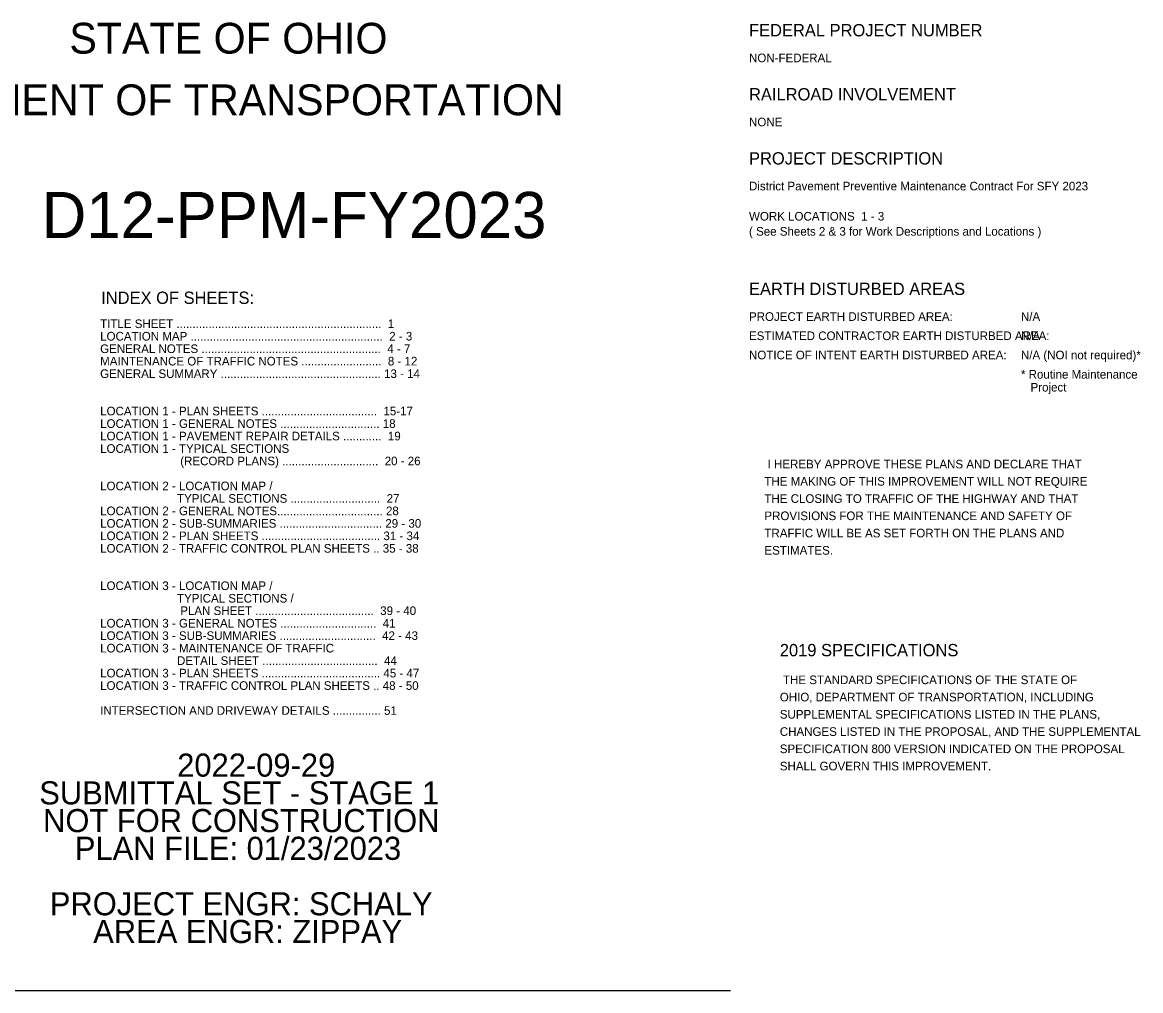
# Model space of a CAD drawing. Extents: x -59 to 82, y -3 to 49.
# Drawn here: x -47.61 to -29.45, y 3.5 to 19.22 of the extents above; entities that cross this region are included whole.
import ezdxf

# ---------------------------------------------------------------- set-up
doc = ezdxf.new("R2010")
doc.units = 0
for name, color, linetype in [('Default', 7, 'Continuous'), ('SH_Data', 7, 'Continuous'), ('SH_Text', 7, 'Continuous')]:
    doc.layers.add(name, color=color, linetype=linetype)

msp = doc.modelspace()

# ---------------------------------------------------------------- linework, layer by layer
at = {"layer": 'SH_Data'}
for p, q in [((-35.312, 7.218), (-35.312, 7.218)), ((-49.562, 3.503), (-36.112, 3.503))]:
    msp.add_line(p, q, dxfattribs=at)

# ---------------------------------------------------------------- texts
at = {"layer": 'Default'}
msp.add_text('D12-PPM-FY2023', height=0.75, dxfattribs=at).set_placement((-47.294, 15.717))
at = {"layer": 'SH_Data'}
for s, height, p in [('District Pavement Preventive Maintenance Contract For SFY 2023', 0.14, (-35.812, 16.492)), ('WORK LOCATIONS  1 - 3', 0.14, (-35.812, 16.002)), ('( See Sheets 2 & 3 for Work Descriptions and Locations )', 0.14, (-35.812, 15.757)), ('INDEX OF SHEETS:', 0.2, (-46.328, 14.649)), ('TITLE SHEET ................................................................  1', 0.14, (-46.345, 14.257)), ('LOCATION MAP ............................................................  2 - 3', 0.14, (-46.345, 14.055)), ('GENERAL NOTES ........................................................  4 - 7', 0.14, (-46.345, 13.852)), ('MAINTENANCE OF TRAFFIC NOTES .........................  8 - 12', 0.14, (-46.345, 13.65)), ('GENERAL SUMMARY .................................................. 13 - 14', 0.14, (-46.345, 13.447)), ('LOCATION 1 - PLAN SHEETS ....................................  15-17', 0.14, (-46.345, 12.84)), ('LOCATION 1 - GENERAL NOTES ............................... 18', 0.14, (-46.345, 12.637)), ('LOCATION 1 - PAVEMENT REPAIR DETAILS ............  19', 0.14, (-46.345, 12.435)), ('LOCATION 1 - TYPICAL SECTIONS', 0.14, (-46.345, 12.232)), ('                         (RECORD PLANS) ..............................  20 - 26', 0.14, (-46.345, 12.03)), (' I HEREBY APPROVE THESE PLANS AND DECLARE THAT', 0.14, (-35.562, 11.98)), ('THE MAKING OF THIS IMPROVEMENT WILL NOT REQUIRE', 0.14, (-35.562, 11.7)), ('LOCATION 2 - LOCATION MAP / ', 0.14, (-46.345, 11.625)), ('                        TYPICAL SECTIONS ............................  27', 0.14, (-46.345, 11.422)), ('THE CLOSING TO TRAFFIC OF THE HIGHWAY AND THAT', 0.14, (-35.562, 11.42)), ('LOCATION 2 - GENERAL NOTES................................. 28', 0.14, (-46.345, 11.22)), ('PROVISIONS FOR THE MAINTENANCE AND SAFETY OF', 0.14, (-35.562, 11.14)), ('LOCATION 2 - SUB-SUMMARIES ................................ 29 - 30', 0.14, (-46.345, 11.017)), ('LOCATION 2 - PLAN SHEETS ..................................... 31 - 34', 0.14, (-46.345, 10.815)), ('TRAFFIC WILL BE AS SET FORTH ON THE PLANS AND', 0.14, (-35.562, 10.86)), ('LOCATION 2 - TRAFFIC CONTROL PLAN SHEETS .. 35 - 38', 0.14, (-46.345, 10.612)), ('ESTIMATES.', 0.14, (-35.562, 10.58)), ('LOCATION 3 - LOCATION MAP /', 0.14, (-46.345, 10.005)), ('                        TYPICAL SECTIONS /', 0.14, (-46.345, 9.802)), ('                         PLAN SHEET .....................................  39 - 40', 0.14, (-46.345, 9.6)), ('LOCATION 3 - GENERAL NOTES ..............................  41', 0.14, (-46.345, 9.397)), ('LOCATION 3 - SUB-SUMMARIES ..............................  42 - 43', 0.14, (-46.345, 9.195)), ('LOCATION 3 - MAINTENANCE OF TRAFFIC', 0.14, (-46.345, 8.992)), ('                        DETAIL SHEET ....................................  44', 0.14, (-46.345, 8.79)), ('LOCATION 3 - PLAN SHEETS ..................................... 45 - 47', 0.14, (-46.345, 8.587)), ('LOCATION 3 - TRAFFIC CONTROL PLAN SHEETS .. 48 - 50', 0.14, (-46.345, 8.385)), ('INTERSECTION AND DRIVEWAY DETAILS ............... 51', 0.14, (-46.345, 7.98))]:
    msp.add_text(s, height=height, dxfattribs=at).set_placement(p)
at = {"layer": 'SH_Text'}
for s, height, p in [('STATE OF OHIO', 0.5, (-46.844, 18.712)), ('FEDERAL PROJECT NUMBER', 0.2, (-35.812, 18.992)), ('NON-FEDERAL', 0.14, (-35.812, 18.572)), ('DEPARTMENT OF TRANSPORTATION', 0.5, (-50.892, 17.712)), ('RAILROAD INVOLVEMENT', 0.2, (-35.812, 17.952)), ('NONE', 0.14, (-35.812, 17.532)), ('PROJECT DESCRIPTION', 0.2, (-35.812, 16.912)), ('EARTH DISTURBED AREAS', 0.2, (-35.812, 14.794)), ('PROJECT EARTH DISTURBED AREA:', 0.14, (-35.812, 14.374)), ('N/A', 0.14, (-31.398, 14.374)), ('ESTIMATED CONTRACTOR EARTH DISTURBED AREA:', 0.14, (-35.812, 14.062)), ('N/A', 0.14, (-31.398, 14.062)), ('NOTICE OF INTENT EARTH DISTURBED AREA:', 0.14, (-35.812, 13.75)), ('N/A (NOI not required)*', 0.14, (-31.398, 13.75)), ('* Routine Maintenance', 0.14, (-31.398, 13.437)), ('   Project', 0.14, (-31.398, 13.227)), ('2019 SPECIFICATIONS', 0.2, (-35.312, 8.93)), (' THE STANDARD SPECIFICATIONS OF THE STATE OF', 0.14, (-35.312, 8.478)), ('OHIO, DEPARTMENT OF TRANSPORTATION, INCLUDING', 0.14, (-35.312, 8.198)), ('SUPPLEMENTAL SPECIFICATIONS LISTED IN THE PLANS,', 0.14, (-35.312, 7.918)), ('CHANGES LISTED IN THE PROPOSAL, AND THE SUPPLEMENTAL', 0.14, (-35.312, 7.638)), ('SPECIFICATION 800 VERSION INDICATED ON THE PROPOSAL', 0.14, (-35.312, 7.358)), ('2022-09-29', 0.375, (-45.094, 6.976)), ('SHALL GOVERN THIS IMPROVEMENT.', 0.14, (-35.312, 7.078)), ('SUBMITTAL SET - STAGE 1', 0.375, (-47.333, 6.526)), ('NOT FOR CONSTRUCTION', 0.375, (-47.272, 6.076)), ('PLAN FILE: 01/23/2023', 0.375, (-46.755, 5.626)), ('PROJECT ENGR: SCHALY', 0.375, (-47.162, 4.726)), ('AREA ENGR: ZIPPAY', 0.375, (-46.458, 4.276))]:
    msp.add_text(s, height=height, dxfattribs=at).set_placement(p)

doc.saveas('drawing.dxf')
